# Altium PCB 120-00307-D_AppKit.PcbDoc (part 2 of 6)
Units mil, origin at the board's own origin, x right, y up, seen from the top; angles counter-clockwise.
Board outline 5150 x 3100 mil, 6 copper layers (L1, L2 (GND), L3-SIG, L4-SIG, L5 (PWR), L6), stack 61.956 mil thick; 413 components, 344 nets, 1685 pads, 1021 vias.
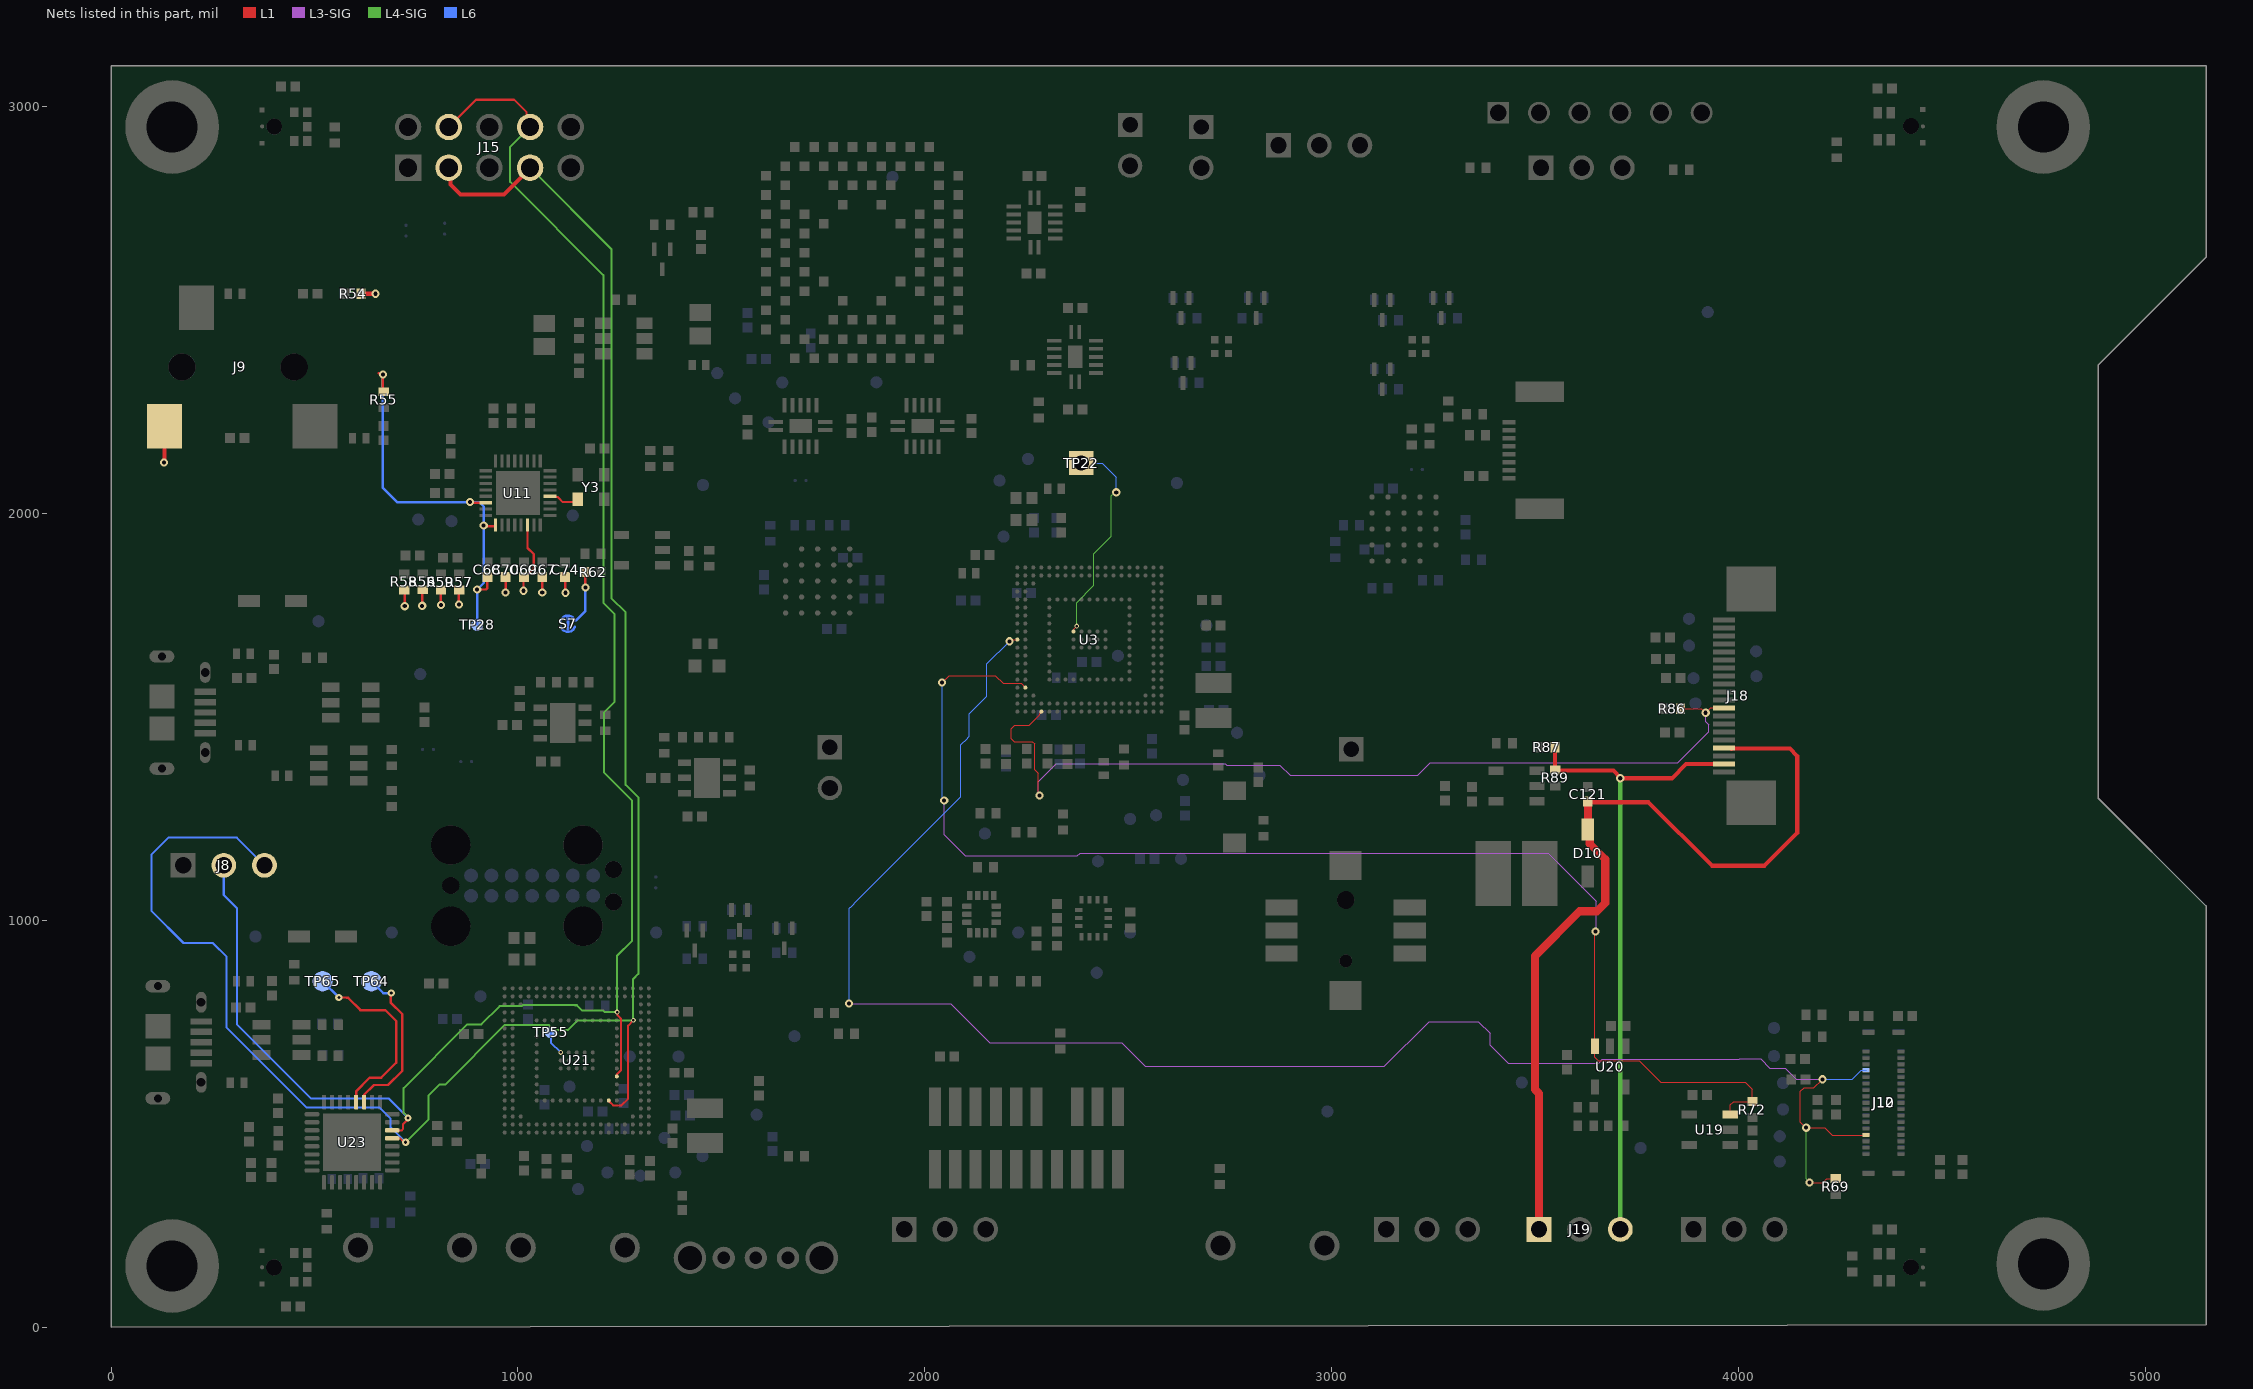
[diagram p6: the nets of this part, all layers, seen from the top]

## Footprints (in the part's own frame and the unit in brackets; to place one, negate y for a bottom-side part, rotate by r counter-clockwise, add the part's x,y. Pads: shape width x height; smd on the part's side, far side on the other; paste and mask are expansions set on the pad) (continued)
Solderbridge_Shorted#3 [mm]
  round 0.2 smd paste-10: 1(-0.338,0) 2(0.338,0)
  L1 region: 0.102,0.432 0.178,0.505 0.296,0.467 0.361,0.424 0.434,0.351 0.488,0.292 0.546,0.193 0.574,0.099 0.569,-0.122 0.544,-0.193 0.46,-0.33 0.376,-0.411 0.284,-0.469 0.183,-0.5 0.132,-0.483 0.102,-0.43
  L1 region: -0.102,-0.432 -0.178,-0.505 -0.296,-0.467 -0.361,-0.424 -0.434,-0.351 -0.488,-0.292 -0.546,-0.193 -0.574,-0.099 -0.569,0.122 -0.544,0.193 -0.46,0.33 -0.376,0.411 -0.284,0.469 -0.183,0.5 -0.132,0.483 -0.102,0.43
  L1 lines w0.152: -0.178,0.431 ccw(c-0.068,0) -0.178,-0.431 ; 0.178,0.431 cw(c0.068,0) 0.494,-0.127 cw(c0.068,0) 0.178,-0.431
  L1 lines w0.203: -0.338,0 0.338,0
Solderbridge_Shorted#4 [mm]
  round 0.2 smd paste-10: 1(-0.338,0) 2(0.338,0)
  L1 region: 0.102,0.432 0.178,0.505 0.296,0.467 0.361,0.424 0.434,0.351 0.488,0.292 0.546,0.193 0.574,0.099 0.569,-0.122 0.544,-0.193 0.46,-0.33 0.376,-0.411 0.284,-0.469 0.183,-0.5 0.132,-0.483 0.102,-0.43
  L1 region: -0.102,-0.432 -0.178,-0.505 -0.296,-0.467 -0.361,-0.424 -0.434,-0.351 -0.488,-0.292 -0.546,-0.193 -0.574,-0.099 -0.569,0.122 -0.544,0.193 -0.46,0.33 -0.376,0.411 -0.284,0.469 -0.183,0.5 -0.132,0.483 -0.102,0.43
  L1 lines w0.152: -0.178,0.431 ccw(c-0.068,0) -0.178,-0.431 ; 0.178,0.431 cw(c0.068,0) 0.178,-0.431
  L1 lines w0.203: -0.338,0 0.338,0
Solderbridge_Shorted#5 [mm]
  round 0.2 smd paste-10: 1(-0.338,0) 2(0.338,0)
  L1 region: 0.102,0.432 0.178,0.505 0.296,0.467 0.361,0.424 0.434,0.351 0.488,0.292 0.546,0.193 0.574,0.099 0.569,-0.122 0.544,-0.193 0.46,-0.33 0.376,-0.411 0.284,-0.469 0.183,-0.5 0.132,-0.483 0.102,-0.43
  L1 region: -0.102,-0.432 -0.178,-0.505 -0.296,-0.467 -0.361,-0.424 -0.434,-0.351 -0.488,-0.292 -0.546,-0.193 -0.574,-0.099 -0.569,0.122 -0.544,0.193 -0.46,0.33 -0.376,0.411 -0.284,0.469 -0.183,0.5 -0.132,0.483 -0.102,0.43
  L1 lines w0.152: -0.178,-0.431 cw(c-0.068,0) -0.254,0.404 cw(c-0.068,0) -0.178,0.431 ; 0.178,-0.431 ccw(c0.068,0) 0.279,0.391 ccw(c0.068,0) 0.254,0.404 ccw(c0.068,0) 0.203,0.423 ccw(c0.068,0) 0.178,0.431
  L1 lines w0.203: -0.338,0 0.338,0
Solderbridge_Shorted#6 [mm]
  round 0.2 smd paste-10: 1(-0.338,0) 2(0.338,0)
  L1 region: 0.102,0.432 0.178,0.505 0.296,0.467 0.361,0.424 0.434,0.351 0.488,0.292 0.546,0.193 0.574,0.099 0.569,-0.122 0.544,-0.193 0.46,-0.33 0.376,-0.411 0.284,-0.469 0.183,-0.5 0.132,-0.483 0.102,-0.43
  L1 region: -0.102,-0.432 -0.178,-0.505 -0.296,-0.467 -0.361,-0.424 -0.434,-0.351 -0.488,-0.292 -0.546,-0.193 -0.574,-0.099 -0.569,0.122 -0.544,0.193 -0.46,0.33 -0.376,0.411 -0.284,0.469 -0.183,0.5 -0.132,0.483 -0.102,0.43
  L1 lines w0.203: 0.338,0 -0.338,0
SSOT-6 [mm]
  rect 0.7x1 smd: 1(-0.95,-1.3) 2(0,-1.3) 3(0.95,-1.3) 4(0.95,1.3) 5(0,1.3) 6(-0.95,1.3)
  silkscreen extent -1.73,-1.17 1.5,0.8, body extent -1.48,-1.38 1.48,1.38, height 1.1
SW_1825966-TL1107-1 [mm]
  round 1.875 hole 1.25: 1(-3.25,0) 2(3.25,0)
  silkscreen extent -3,-1.75 3,1.75, body extent -3.9,-1.78 4,1.72, height 4.7
SW_JS1400BFQ [mm]
  rect 2x1 smd: 1(-4,1.425) 2(-4,0) 3(-4,-1.425) 4(4,1.425) 5(4,0) 6(4,-1.425)
  rect 2x1.8 smd: SH1(0,4.05) SH2(0,-4.05)
  round 0.8 hole 0.8 unplated: ""(0,1.9)
  round 1.1 hole 1.1 unplated: ""(0,-1.9)
  silkscreen extent -3.85,-3.7 3.85,3.7, body extent -4.5,-3.9 4.5,3.9, height 4.99
SW_SPDT_OS10201MSQN1 [mil] "Switch, SPDT slide, PCB vertical, 5 pin"
  round 55 hole 31: 1(-79,0) 2(0,0) 3(79,0)
  round 80 hole 59: 4(-162,0) 5(162,0)
  silkscreen extent -177,-109 176,90, body extent -168,-86 170,84, height 353
TC2070-IDC [mil]
  round 34 smd paste-42: 1(-150,-25) 2(-100,-25) 3(-50,-25) 4(0,-25) 5(50,-25) 6(100,-25) 7(150,-25) 8(150,25) 9(100,25) 10(50,25) 11(0,25) 12(-50,25) 13(-100,25) 14(-150,25)
  round 96.5 hole 96.5 unplated: 15(-200,100) 17(-200,-100) 18(125,-100) 21(125,100)
  round 42 hole 42 unplated: 16(-200,0) 19(200,-39.96) 20(200,39.96)
  silkscreen extent -249,-102 245,98
TP_30_RND [mil]
  round 30 smd paste-15: 1(0,0)
  silkscreen extent -22,-22 22,22
TP_50_RND [mil]
  round 50 smd paste-25: 1(0,0)
  silkscreen extent -32,-32 32,32
TSOT23-5_ONS [mil]
  rect 37.5x20 smd paste+0 mask+4: 1(-50.25,37.4) 2(-50.25,0) 3(-50.25,-37.4) 4(50.25,-37.4) 5(50.25,37.4)
  silkscreen extent -65,-62 37,75, body extent -55,-57 55,57, height 39
WE-TVS_SOT23-6L [mm] "TVS Diode, package SOT23-6L"
  rect 0.6x1.1 smd: 1(-0.95,-1.25) 2(0,-1.25) 3(0.95,-1.25) 4(0.95,1.25) 5(0,1.25) 6(-0.95,1.25)
  silkscreen extent -1.72,-1.37 1.45,0.45, body extent -1.45,-1.4 1.45,1.4, height 1.16
XTAL_ABS07_ABR-M [mil]
  rect 46x57 smd paste+0: 1(-64,0) 2(64,0)
  silkscreen extent -29,-33 29,33, body extent -65,-27 65,27, height 35

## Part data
C1 C7 C12 C13 C29 C30 C32 C33 C34 C35 C36 C73 C93 C95 C98 C99 C109 C112 C113 C114 C115 C128 C131 C141: "Cap,1.0uF,20%,25V,X5R,0402", Manufacturer 1=TDK, Manufacturer 2=Yageo, Manufacturer 3=Murata, Manufacturer Part Number 1=CGB2A1X5R1E105K033BC, Manufacturer Part Number 2=CC0402KRX5R8BB105, Manufacturer Part Number 3=GRM155R61E105KA12D, Tolerance=10%, Voltage=25V
C2 C5 C14 C49 C74 C88 C90 C92 C94 C96 C100 C117 C119: "Cap,10uF,20%,10V,X5R,0402", Manufacturer 1=AVX, Manufacturer 2=Samsung, Manufacturer 3=Venkel, Manufacturer Part Number 1=0402ZD106MAT2A, Manufacturer Part Number 2=CL05A106MP5NUNC, Manufacturer Part Number 3=C0402X5R100-106MNP, Tolerance=10%, Voltage=10V
C3 C8 C76: "Cap,10nF,10%,50V,X7R,0402", Manufacturer 1=TDK, Manufacturer 2=Samsung, Manufacturer 3=Walsin, Manufacturer Part Number 1=CGA2B3X7R1H103K050BE, Manufacturer Part Number 2=CL05B103KB5NNNC, Manufacturer Part Number 3=0402B103K500CT, Tolerance=10%, Voltage=50V
C4 C6 C11 C63 C71 C72 C78 C85 C86 C87 C89 C91 C97 C121 C122 C124: "Cap,2.2uF,20%,25V,X5R,0402", Manufacturer 1=TDK, Manufacturer 2=Murata, Manufacturer Part Number 1=C1005X5R1E225M050BC, Manufacturer Part Number 2=GRM155R61E225ME11D, Manufacturer Part Number 3=GRM155R61E225ME15D, Tolerance=20%, Voltage=25V
C9 C10 C15 C16 C17 C18 C19 C20 C21 C22 C23 C25 C26 C27 C28 C31 C37 C38 C39 C40 C41 C42 C45 C46 C47 C48 C57 C58 C59 C61 C62 C64 C65 C67 C75 C77 C79 C80 C81 C82 C83 C84 C101 C102 C103 C104 C105 C106 C107 C108 C110 C111 C116 C118 C120 C123 C125 C129 C133 C134: "Cap,100nF,10%,50V,X7R,0402", Manufacturer 1=TDK, Manufacturer 2=Samsung, Manufacturer 3=Walsin, Manufacturer Part Number 1=C1005X7R1H104K050BE, Manufacturer Part Number 2=CL05B104KB54PNC, Manufacturer Part Number 3=0402B104K500CT, Tolerance=10%, Voltage=50V
C24 C43 C44 C55 C56: "DNI, Cap,100nF,10%,50V,X7R,0402", Manufacturer 1=TDK, Manufacturer 2=Samsung, Manufacturer 3=Walsin, Manufacturer Part Number 1=C1005X7R1H104K050BE, Manufacturer Part Number 2=CL05B104KB54PNC, Manufacturer Part Number 3=0402B104K500CT, Tolerance=10%, Voltage=50V
C50 C51 C53 C60: "Cap,100pF,5%,25V,C0G,Hi-Q,0402", Manufacturer 1=Kemet, Manufacturer 3=Walsin, Manufacturer Part Number 1=CBR04C101J3GAC, Manufacturer Part Number 2=CBR04C101G3GAC, Manufacturer Part Number 3=RF15N101J250CT, Tolerance=5%, Voltage=25V
C52 C54: "Cap,100uF,20%,6.3V,X5R,0805", Manufacturer 1=MuRata, Manufacturer 2=Samsung, Manufacturer 3=Venkel, Manufacturer Part Number 1=GRM21BR60J107ME15K, Manufacturer Part Number 2=CL21A107MQYNNWE, Manufacturer Part Number 3=C0805X5R6R3-107MNE, Tolerance=20%, Voltage=6V3
C66 C68 C69 C70 C130 C132: library part Cap_225M25VX5R0402_1, "Cap,4.7uF,20%,10V,X5R,0402", Manufacturer 1=TDK, Manufacturer 2=Kyocera, Manufacturer 3=Samsung, Manufacturer Part Number 1=C1005X5R1A475K050BC, Manufacturer Part Number 2=0402YD475MAT2A, Manufacturer Part Number 3=CL05A475MP5NRNC, Tolerance=20%, Voltage=10V
C126 C127: library part Cap_SMT, "DNI,Cap,100pF,5%,50V,C0G,0402", Manufacturer 1=Kemet, Manufacturer 3=Walsin, Manufacturer Part Number 1=CBR04C101J3GAC, Manufacturer Part Number 2=CBR04C101G3GAC, Manufacturer Part Number 3=RF15N101J250CT, Tolerance=5%, Voltage=50V
D1 D3 D5: library part 82400102, "Diode,TVS  – High Speed Series, SOT23-6L, 2+1 Channel, 5Vdc, 2pF", Channel ESD Clamping Voltage=10V, Channel Input Capacitance=2pF, Channel Operating Voltage=5V, Channel Reverse Leakage Current=1uA, Manufacturer="Wurth Elektronik", Manufacturer 1=Wurth, Operating Temperature max.=125C, Operating Temperature min.=-40C, Reverse Breakdown Voltage=6V, Reverse Peak Pulse Current=7A
D2: "Diode,LED,Green 573nm,300mcd @ 20mA,0603", Manufacturer 1=Wurth, Manufacturer Part Number 1=150060VS86000
D4 D6 D9: library part "D LED_RGB_CA_1MMc1MM", "Diode,LED,RGB, (@2mA) -> R=10mcd & 1.75V, G = 50mcd & 2.75V, B = 20mcd & 2.95V, 0404(1mm x 1mm)", Manufacturer 1=Lumex
D7 D8 D10: "Diode,Schottky,2A,60V, <50uA@60V,SOD123F", Manufacturer 1=OnSemi, Manufacturer 2=Rohm, Manufacturer 3=Panjit, Manufacturer Part Number 1=SS26FL, Manufacturer Part Number 2=RB060MM-60TR, Manufacturer Part Number 3=SS2060FL_R1_00001
FB1 FB2 FB3 FB4 FB5 FB7 FB8 FB10 FB11 FB12: "Ind,WidebandChoke,1.5A,120ohm@100MHz,95mOhm,0402", Manufacturer 1=MuRata, Manufacturer Part Number 1=BLM15EG121SN1D, RMS_Current=1.5A
FB6 FB9: "DNI, Ind,WidebandChoke,1.5A,120ohm@100MHz,95mOhm,0402", Manufacturer 1=MuRata, Manufacturer Part Number 1=BLM15EG121SN1D, RMS_Current=1.5A
H1 H2 H3 H4: "Hole, #4,--not a BOM item--"
J1 J2: library part Conn_USB-5-6SHLD, "Conn,Micro USB B Type Receptacle,Right Angle", Manufacturer="Amphenol FCI", Manufacturer Part Number 1=10118194-0001LF, Package Description="5-Pin Surface Mount Device, Body 8.05 x 5.53 mm, Pitch 0.65 mm"
J3 J4 J21: library part Hdr_M_1X2_2M54_STRT_UNSHROUD, "Hdr, 0.025\" SQ Post Header, Through-hole, Vertical, -55 to 125 degC, 2.54 mm Pitch, 2-Pin, Male, RoHS", Manufacturer=Samtec, Manufacturer 2=Amphenol, Manufacturer Part Number 1=TSW-102-07-L-S, Manufacturer Part Number 2=77311-102-02LF, Temperature Range="-55 to 125 degC"
J5 J6 J11 J13 J16 J19: library part Hdr_M_1X3_2M54_STRT_UNSHROUD, "Hdr, 0.025\" SQ Post Header, Through-hole, Vertical, -55 to 125 degC, 2.54 mm Pitch, 3-Pin, Male, RoHS", Manufacturer=Samtec, Manufacturer 2=Sullins, Manufacturer 3=3M, Manufacturer Part Number 1=TSW-103-07-L-S, Manufacturer Part Number 2=PRPC003SAAN-RC, Manufacturer Part Number 3=929647-01-03-I, Temperature Range="-55 to 125 degC"
J7: library part Hdr_M_1X6_2M54_STRT_UNSHROUD, "Hdr, 0.025\" SQ Post Header, Through-hole, Vertical, -55 to 125 degC, 2.54 mm Pitch, 5-Pin, Male, RoHS", Manufacturer=Samtec, Temperature Range="-55 to 125 degC"
J8: library part Hdr_M_1X3_2M54_STRT_UNSHROUD, "DNI,Hdr, 0.025\" SQ Post Header, Through-hole, Vertical, -55 to 125 degC, 2.54 mm Pitch, 3-Pin, Male, RoHS", Manufacturer=Samtec, Manufacturer 2=Sullins, Manufacturer 3=3M, Manufacturer Part Number 2=PRPC003SAAN-RC, Manufacturer Part Number 3=929647-01-03-I, Temperature Range="-55 to 125 degC"
J9: library part CONN_AUDIO_SJ-3523-SMT-TR, "Conn, Audio Jack, 3.5 mm Low Profile Surface Mount Stereo Jack, 3 Pin Right-Angle", Manufacturer 1=CUI, Manufacturer Part Number 1=SJ-3523-SMT-TR, Package=None
J10 J12: library part CONN_HIROSE_BM20_FPC_34PIN_0.4MM, "Conn,FPC,34 pin,0.4mm pitch, 0,8mm height,SMT", Manufacturer 1=HiRose
J14: "Test Point, Array, Alignment Pins, SMT Pad,--not a BOM item--"
J15: library part Hdr_M_2X5_2M54_STRT_UNSHROUDED, "Hdr, Male,2x5, 2.54mm, 0.230mate,0.100-0.120post,Strt", Manufacturer 1=Samtec, Manufacturer 2=Sullins, Manufacturer Part Number 1=TSW-105-07-L-D, Manufacturer Part Number 2=PBC05DAAN, Manufacturer Part Number 3=TSW-105-07-F-D
J17: "Hdr,Male,2x10,1.27mm,Strt,Keyed,Cortex-JTAG", Manufacturer 1=Samtec, Manufacturer Part Number 1=FTSH-110-01-L-DV-007-K
J18: library part Conn_FFC_TOP_SLIDEorLOCK_0.50_20pin, "Conn,FlatFlex,20 pin,0.50mm,top-entry,slide-flap,SMT", Manufacturer 1=Amphenol, Manufacturer 2=Molex, Manufacturer Part Number 2=0527452097
J20: library part Conn_FFC_TOP_SLIDorLOCK_0.50_8pin, "Conn,FlatFlex,8 pin,0.50mm,top-entry,slide-flap,SMT", Manufacturer 1=Amphenol, Manufacturer 2=Molex, Manufacturer 3=TE, Manufacturer Part Number 2=0527450897, Manufacturer Part Number 3=1734839-8, Mfr_Name=Omron
L3 L4: "Ind,Unshielded,2.2uH,20%,2.3A,85mOhm,1008(2520)", Manufacturer 1=MuRata, Manufacturer 2="Pulse Eng", Manufacturer 3=Vishay, Manufacturer Part Number 1=DFE252012F-2R2M{}P2, Manufacturer Part Number 2=BDHE002520122R2MQ1, Manufacturer Part Number 3=IHHP1008ABER2R2M01, RMS_Current=2.3A, Tolerance=20%
L5: "Ind,Shielded,22uH,20%,700mA,350mOhm,4x4x2mm", Manufacturer 1=Vishay, Manufacturer 2=Yageo, Manufacturer 3=Abracon, Manufacturer Part Number 1=IFSC1515AHER220M0, Manufacturer Part Number 2=BWVS00404018220M00, Manufacturer Part Number 3=ASPI-0418FS-220M-T3, RMS_Current=700mA, Tolerance=20%
Q1 Q2 Q3 Q4 Q5 Q6 Q8 Q9 Q10 Q11: "MOSFET,N-CH,20V,250mA,1.1Ohm,SOT-23", Manufacturer 1=Toshiba, Manufacturer 2=Rohm, Manufacturer Part Number 1=SSM3K35AFS, Manufacturer Part Number 2=RUE002N02TL
Q7: library part FET_PMOS_6P, "MOSFET,P-CH,20V,4.5A,48mOhm,SSOT-6", Continuous Drain Current=-4.5A, Drain To Source Breakdown Voltage=-20V, Drain To Source Resistance=0.041Ω, Drain To Source Voltage=-30V, Gate To Source Voltage=20V, Input Capacitace At Vds="750pF @ -15V", Manufacturer="ON Semiconductor", Manufacturer 1=OnSemi, Manufacturer 2=Fairchild, Manufacturer Part Number 1=FDC658P, Max Forward Diode Voltage=-1.2V, Max Junction Temp=+150°C, Power Dissipation=0.8W, Pulse Drain Current=-20A, Temperature="-55°C to +150°C", Temperature Range Low=-55°C, Typ Forward Diode Voltage=-0.76V
R1 R56 R57: "Res,33K2,1%,100ppm,0402", Manufacturer 1=Stackpol, Manufacturer 2=Yageo, Manufacturer 3=Bourns, Manufacturer Part Number 1=RMCF0402FT33K2, Manufacturer Part Number 2=RC0402FR-0733K2L, Manufacturer Part Number 3=CR0402-FX-3322GLF, Tolerance=1%
R2 R16 R32 R33 R34 R35 R97 R98 R105 R106 R107 R108 R109 R110: "Res,0R ohm,Jumper,0402", Manufacturer 1=Stackpol, Manufacturer 2=Yageo, Manufacturer 3=Panasonic, Manufacturer Part Number 1=RMCF0402ZT0R00, Manufacturer Part Number 2=RC0402FR-070RL, Manufacturer Part Number 3=ERJ-XGN0R00Y, Tolerance=JMPR
R3 R9 R12 R26 R31 R61 R69 R71 R86 R90 R93 R101 R104: "Res,10K0,1%,100ppm,0402", Manufacturer 1=Stackpol, Manufacturer 2=Yageo, Manufacturer 3=Bourns, Manufacturer Part Number 1=RMCF0402FT10K0, Manufacturer Part Number 2=RC0402FR-0710KL, Manufacturer Part Number 3=CR0402-FX-1002GLF, Tolerance=1%
R4 R8 R10 R62 R74 R100 R103: "Res,20K0,1%,100ppm,0402", Manufacturer 1=Stackpol, Manufacturer 2=Yageo, Manufacturer 3=Bourns, Manufacturer Part Number 1=RMCF0402FT20K0, Manufacturer Part Number 2=RC0402FR-0720KL, Manufacturer Part Number 3=CR0402-FX-2002GLF, Tolerance=1%
R5 R48 R49 R50 R51 R52 R53: "Res,1K82,1%,100ppm,0402", Manufacturer 1=Stackpol, Manufacturer 2=Yageo, Manufacturer 3=Bourns, Manufacturer Part Number 1=RMCF0402FT1K82, Manufacturer Part Number 2=RC0402FR-071K82L, Manufacturer Part Number 3=CR0402-FX-1821GLF, Tolerance=1%
R6 R11 R29 R30: "DNI,Res,100K,1%,100ppm,0402", Manufacturer 1=Stackpol, Manufacturer 2=Yageo, Manufacturer 3=Bourns, Manufacturer Part Number 1=RMCF0402FT100K, Manufacturer Part Number 2=RC0402FR-07100KL, Manufacturer Part Number 3=CR0402-FX-1003GLF, Tolerance=1%
R7: "Res,8K66,1%,100ppm,0402", Manufacturer 1=Stackpol, Manufacturer 2=Yageo, Manufacturer 3=Bourns, Manufacturer Part Number 1=RMCF0402FT8K66, Manufacturer Part Number 2=RC0402FR-078K66L, Manufacturer Part Number 3=CR0402-FX-8661GLF, Tolerance=1%
R13 R20 R79: "Res,681R,1%,100ppm,0402", Manufacturer 1=Stackpol, Manufacturer 2=Yageo, Manufacturer 3=Bourns, Manufacturer Part Number 1=RMCF0402FT681R, Manufacturer Part Number 2=RC0402FR-07681RL, Manufacturer Part Number 3=CR0402-FX-6810GLF, Tolerance=1%
R14 R17 R21 R23 R41 R80 R82 R87: "Res,1K00,1%,100ppm,0402", Manufacturer 1=Stackpol, Manufacturer 2=Yageo, Manufacturer 3=Bourns, Manufacturer Part Number 1=RMCF0402FT1K, Manufacturer Part Number 2=RC0402FR-071KL, Manufacturer Part Number 3=CR0402-FX-1001GLF, Tolerance=1%
R15 R18 R19 R22 R24 R25 R27 R28 R39 R40 R43 R44 R45 R60 R63 R66 R72 R78 R81 R83 R84 R85 R88 R94: "Res,100K,1%,100ppm,0402", Manufacturer 1=Stackpol, Manufacturer 2=Yageo, Manufacturer 3=Bourns, Manufacturer Part Number 1=RMCF0402FT100K, Manufacturer Part Number 2=RC0402FR-07100KL, Manufacturer Part Number 3=CR0402-FX-1003GLF, Tolerance=1%
R36 R37 R76: "Res,200R,1%,100ppm,0402", Manufacturer 1=Stackpol, Manufacturer 2=Yageo, Manufacturer 3=Bourns, Manufacturer Part Number 1=RMCF0402FT220R, Manufacturer Part Number 2=RC0402FR-07200RL, Manufacturer Part Number 3=CR0402-FX-2000GLF, Tolerance=1%
R42 R75 R95 R96 R111: "DNI,Res,0R ohm,Jumper,0402", Manufacturer 1=Stackpol, Manufacturer 2=Yageo, Manufacturer 3=Panasonic, Manufacturer Part Number 1=RMCF0402ZT0R00, Manufacturer Part Number 2=RC0402FR-070RL, Manufacturer Part Number 3=ERJ-XGN0R00Y, Tolerance=JMPR
R46 R47 R92: "DNI,Res,4K75,1%,100ppm,0402", Manufacturer 1=Stackpol, Manufacturer 2=Yageo, Manufacturer 3=Bourns, Manufacturer Part Number 1=RMCF0402FT4K75, Manufacturer Part Number 2=RC0402FR-074K75L, Manufacturer Part Number 3=CR0402-FX-4751GLF, Tolerance=1%
R54 R55 R58 R59: "Res,20R0,1%,100ppm,0402", Manufacturer 1=Stackpol, Manufacturer 2=Yageo, Manufacturer 3=Bourns, Manufacturer Part Number 1=RMCF0402FT20R, Manufacturer Part Number 2=RC0402FR-0720RL, Manufacturer Part Number 3=CR0402-FX-20R0GLF, Tolerance=1%
R64 R65 R67 R68: "Res,33R2,1%,100ppm,0402", Manufacturer 1=Stackpol, Manufacturer 2=Yageo, Manufacturer 3=Bourns, Manufacturer Part Number 1=RMCF0402FT33R2, Manufacturer Part Number 2=RC0402FR-0733R2L, Manufacturer Part Number 3=CR0402-FX-33R2GLF, Tolerance=1%
R70: "Res,23K7,1%,100ppm,0402", Manufacturer 1=Stackpol, Manufacturer 2=Yageo, Manufacturer 3=Bourns, Manufacturer Part Number 1=RMCF0402FT23K7, Manufacturer Part Number 2=RC0402FR-0723K7L, Manufacturer Part Number 3=CR0402-FX-2372GLF, Tolerance=1%
R73: "Res,150K,1%,100ppm,0402", Manufacturer 1=Stackpol, Manufacturer 2=Yageo, Manufacturer 3=Bourns, Manufacturer Part Number 1=RMCF0402FT150K, Manufacturer Part Number 2=RC0402FR-07150KL, Manufacturer Part Number 3=CR0402-FX-1503GLF, Tolerance=1%
R89: "Res,7R50,1%,100ppm,0402", Manufacturer 1=Stackpol, Manufacturer 2=Yageo, Manufacturer Part Number 1=RMCF0402FT7R5, Manufacturer Part Number 2=RC0402FR-077R5L, Tolerance=1%
R91 R99 R102: "Res,4K75,1%,100ppm,0402", Manufacturer 1=Stackpol, Manufacturer 2=Yageo, Manufacturer 3=Bourns, Manufacturer Part Number 1=RMCF0402FT4K75, Manufacturer Part Number 2=RC0402FR-074K75L, Manufacturer Part Number 3=CR0402-FX-4751GLF, Tolerance=1%
S1 S2 S3 S5 S6 S7 S8 S9: "DNI,Solderable Jumper,Shorted"
SW1 SW4 SW5: "Swit, SPST, Momentary Pushputton, 2 pin, 6.0x3.5mm, H=5.0mm", Manufacturer 1=E-Switch, Manufacturer 2=C&K, Manufacturer 3=Panasonic, Manufacturer Part Number 1=TL1107BF180WQ, Manufacturer Part Number 2="PTS636 SM50 LFS", Manufacturer Part Number 3=EVQ-PE505K
SW2: "Navigation Switch, 2 - Axis Digital (Mechanical Switch) Output", Manufacturer 1=ESwitch, Manufacturer 2=Diptronics, Manufacturer Part Number 1=JS1400BFQ, Manufacturer Part Number 2=MT5-1F-V, Package=None
SW3: library part SW-SPDT_Vert-5P, "Switch,SPDT, 12V, 50mA, Non-Shorting, 5 Pin PCB Vertical", Manufacturer 1=C&K, Manufacturer 3=E-Switch, Manufacturer Part Number 1=OS102011MS2QN1, Manufacturer Part Number 2=OS102011MS2QN1C, Manufacturer Part Number 3=EG1249
TP1 TP2 TP3 TP4 TP5 TP6 TP7 TP8 TP9 TP10 TP11 TP12 TP13 TP14 TP15 TP16 TP17 TP18 TP19 TP20 TP21 TP25 TP26 TP27 TP28 TP29 TP30 TP31 TP32 TP33 TP34 TP35 TP36 TP37 TP38 TP39 TP40 TP41 TP42 TP43 TP44 TP45 TP46 TP47 TP48 TP49 TP50 TP51 TP52 TP53 TP54 TP55 TP56 TP58 TP59 TP60 TP61 TP62 TP63 TP66 TP67 TP68 TP69 TP70: "Test Point, SMT Pad,--not a BOM item--"
TP22 TP23: library part Hdr_M_1X1_2M54_STRT_UNSHROUD, "DNI,Hdr, 0.025\" SQ Post Header, Through-hole, Vertical, -55 to 125 degC, 2.54 mm Pitch, 1-Pin, Male, RoHS", Manufacturer=Samtec, Manufacturer 2=Amphenol, Manufacturer Part Number 1=TSW-101-07-L-S, Manufacturer Part Number 2=77311-101-01LF, Temperature Range="-55 to 125 degC"
TP64 TP65: "DNI,Test Point, SMT Pad,--not a BOM item--"
U1 U2: library part IC_LDO_NCP690MNADJT2G, "IC, LDO,Adj 1.25V - 5.5V,1.0A,+ Enable,DFN6", Manufacturer 1=OnSemi
U3: library part E7_B0_194BGA, "IC,Alif E7 MCU, Rev B silicon, 5.5MB MRAM, 13.5MB SRAM, BGA194", Manufacturer 1="Alif Semi", Manufacturer Part Number 1=AE722F80F55D5LS
U4: "IC, Flash,64MB x 8, Octal SPI, Ind Temp, 1.8V,24-BGA", Manufacturer 1=ISSI, Manufacturer Part Number 1=IS25WX512M-JHLE, Package="BGA-24 Dialog Semiconductor"
U5: "IC, Hyper PSRAM,64MB x 8, Octal SPI, Ind Temp, 1.8V,24-BGA", Manufacturer 1=ISSI, Manufacturer Part Number 1=IS66WVH64M8DALL-166B1LI
U6: library part IC_XLAT_NTB0104BQ, "DNI,IC, Voltage Level Translator, 4-bit,push-pull,50Mbps,VCC(A): 1.2 V to 3.6 V and VCC(B): 1.65 V to 5.5 V,auto-sense,DHVQFN14(2.5x3.0)", Arrow Part Number=NTB0104BQ-Q100X, Manufacturer 1=NXP, Manufacturer Part Number 3=NTB0104BQ,115, Mouser Part Number=771-NTB0104BQQ100X
U7: library part MOD_WE310F5-I, "Module, WIFI (802.11 b/g/n) / BLE (5.0) MODULE, SMD-94P", Manufacturer 1=Telit, Manufacturer Part Number 1=WE310F5I396R001000, Manufacturer Part Number 2=WE310F5I396T001000, Operating_Temp="-40C TO +85C"
U8 U9: library part IC_XLAT_NTB0104BQ, "IC, Voltage Level Translator, 4-bit,push-pull,50Mbps,VCC(A): 1.2 V to 3.6 V and VCC(B): 1.65 V to 5.5 V,auto-sense,DHVQFN14(2.5x3.0)", Arrow Part Number=NTB0104BQ-Q100X, Manufacturer 1=NXP, Manufacturer Part Number 3=NTB0104BQ,115, Mouser Part Number=771-NTB0104BQQ100X
U10: library part IC_XLAT_NTS0104BQ, "DNI,IC, Voltage Level Translator, 4-bit,open-drain,50Mbps,VCC(A): 1.2 V to 3.6 V and VCC(B): 1.65 V to 5.5 V,auto-sense,DHVQFN14(2.5x3.0)", Arrow Part Number=NTB0104BQ-Q100X, Manufacturer 1=NXP, Manufacturer Part Number 2=NTS0104BQ-Q100X, Manufacturer Part Number 3=NTS0104BQ,115, Mouser Part Number=771-NTB0104BQQ100X
U11: library part IC_CODEC_WM8904CGEFL_V, "IC, Audio CODEC, Ultra Low Pwr, 1.8V, QFN33", Manufacturer 1="Cirrus Logic", Manufacturer Part Number 1=WM8904CGEFL/V, Mouser Part Number=238-WM8904CGEFL/V
U12 U19 U20: library part IC_LDO_NCV8164ASNADJT1G, "IC, LDO,Adj 1.2V - 5.5V,300mA,SOT23-5", Manufacturer 1=OnSemi
U13 U15: library part MIC_T5848, "IC,Microphone,I2S,Bottom Port,Sens -37db,SNR 68dbA,AOP 13db SPL,1.8V", Manufacturer 1=TDK/Invensense, Manufacturer Part Number 1=T5848-00-012, Manufacturer_Name=TDK
U14: "IC, IMU Gyro & Accel, I3C, 1.8V, LGA14", Manufacturer 1=TDK_Invensense, Manufacturer Part Number 1=ICM-42670-P
U16: library part IC_IMU_BMI323, "IC,IMU,6 Axis Sensor I3C, SPI, LGA14", Manufacturer 1=Bosch, Package="LGA-14 Bosch"
U17 U18: library part MIC_T5838, "IC,Microphone,PDM,Bottom Port,Sens -37db,SNR 68dbA,AOP 13db SPL,1.8V", Manufacturer 1=TDK, Manufacturer Part Number 1=MMICT5838-00-012
U21: library part E7_B0_194BGA, "IC,Alif E1 MCU, Rev B silicon,1.5MB MRAM, 4.5MB SRAM. BGA194", Manufacturer 1="Alif Semi", Manufacturer Part Number 1=AE101F4071542LH
U22: library part IC_BOOST_CAT4139TD-GT3, "IC, Boost Converter, LED Driver", Manufacturer 1=OnSemi
U23: library part IC_Dual_USB_UART_Bridge, "IC,Dual USB to Serial Bridge,32QFN", Ambient Temperature Range High=+85°C, Ambient Temperature Range Low=-40°C, Manufacturer 1=Cypress, Max Supply Voltage=5.5V, Min Supply Voltage=1.71V, Nominal Supply Current=13mA, Package=001-30999, Temperature="-40°C to +85°C"
Y1 Y4: "Crystal,38.4MHz,20ppm,6.0pF,100ohm,2016-4pin", Manufacturer 1=Murata, Manufacturer Part Number 1=XRCGB38M400F2P00R0
Y2: "Crystal,32.768KHz,20ppm,6.0pF,100ohm,3215-4pin", Manufacturer 1=Abracon, Manufacturer Part Number 1=ABS07-32.768KHZ-6-T
Y3: library part Osc_12M288_20ppm_1V8_3225, "Oscillator,XO,12.288MHz,20ppm,1.8V,3225(1210)-4P", Manufacturer 1=Microchip, Manufacturer 2=Kyocera, Manufacturer 3=SiTime, Manufacturer Part Number 1=DSC1001DL5-012.2880, Manufacturer Part Number 2=KC2520Z12.2880C1KX00, Manufacturer Part Number 3=SIT8008BI-11-18E-12.288000, Tolerance=20ppm

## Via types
v1: diameter 20, hole 10, L1 to L6, tented both sides, 437 vias
v2: diameter 20, hole 10, L1 to L6, 330 vias
v3: diameter 12, hole 6, L1 to L6, tented both sides, 120 vias
v4: diameter 18, hole 8, L1 to L6, 93 vias
v5: diameter 16, hole 8, L1 to L6, tented both sides, 41 vias

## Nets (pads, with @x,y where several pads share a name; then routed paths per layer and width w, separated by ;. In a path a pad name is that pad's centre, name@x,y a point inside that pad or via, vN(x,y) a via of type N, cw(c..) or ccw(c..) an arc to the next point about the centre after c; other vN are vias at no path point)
AG: C67.1 C68.1 C69.1 C70.1 C74.1 J9.1 R54.1 R55.1 R56.2 R57.2 R58.2 R59.2 R62.2 S7.2 TP28.1 U11.14 U11.17 U11.22 | length 1722
  L1 w6: 657.49,2345 657.81,2344.68 667,2344.68 v2@667,2341 ; R55.1@668,2298 v2(668,2342) ; R58.2@719,1810 722,1813 R58.2@721,1813 ; v1(721.84,1771.97) R58.2@721.84,1809.29 ; v1(764.84,1772.97) R56.2@764.84,1810.29 ; v1(810.84,1774.97) R59.2@810.84,1812.29 ; v1(854.84,1775.97) R57.2@854.84,1813.29 ; v1(882,2028) 883.62,2026.38 U11.14@921.26,2026.38 ; v1(900,1813) 921.49,1813 925,1816.51 C68.1@925,1843.6 ; v1@917,1969 943.94,1969 944.88,1969.94 U11.17@944.88,1971.26 ; v1(969.84,1805.97) C70.1@969.84,1843.29 ; v1(1013.84,1809.97) C69.1@1013.84,1847.29 ; C69.1@1015,1843.6 1015.4,1843.6 C69.1@1018,1841 ; U11.22@1023.62,1971.26 1023.62,1915.38 1039,1900 1039,1864 C69.1@1024,1849 ; v1(1059.84,1805.97) C67.1@1059.84,1843.29 ; v1(1116.84,1804.97) C74.1@1116.84,1842.29 ; R62.2@1165.31,1856 1166,1855.31 v1(1166,1818)
  L1 w10: v2(130,2125) 131.1,2126.1 J9.1@131.1,2214.33 ; R54.1@614.68,2540 v2(650,2540)
  L6 w6: v2(668,2342) 668,2063 703,2028 v1(882,2028) 905,2028 916,2017 v1(916,1970) 916,1829 v1(900,1813) TP28.1@900,1728 ; 1139.67,1737 1143,1737 1166,1760 v1(1166,1818)
AMUX_P: TP22.1 U3.J8 | length 525.2
  L1 w3: U3.J8@2365.63,1709.68 2366.82,1710.87 2366.82,1715.82 v3(2374,1723)
  L4-SIG w3: v3(2374,1723) 2374,1781 2416,1823 2416,1901 2459,1944 2459,2043 2468,2052 v2(2471,2052)
  L6 w3: TP22.1@2385,2124 2436,2124 2471,2089 v2(2471,2052)
AMUX_P_J: TP55.1 U21.J8 | length 60.1
  L6 w5: TP55.1@1081,725 1081,699.32 v3(1105.32,675)
BL_LED_A: C121.2 D10.1 J18.4 J19.1 | length 2160.7
  L1 w10: C121.2@3630,1292.28 3630,1291 3631,1290 3779,1290 3935,1134 4065,1134 4145,1214 4145,1404 4127,1422 3984,1422 J18.4@3983,1421 ; J18.4@3965,1423.46 J18.4@3983,1423.46
  L1 w20: J19.1@3510,240 3510,574 3500,584 3500,912 3610,1022 3653,1022 3673,1042 3673,1150 3635,1188 3635,1219 3631,1223 C121.2@3631,1290
BL_LED_K: J18.2 J19.3 R87.1 R89.2 | length 1592.2
  L1 w10: R87.1@3549.37,1425 3550,1424.37 R89.2@3550,1369.37 R89.2@3550,1364 ; R89.2@3552,1368 3693,1368 v2@3711,1350 ; v2(3710,1349) 3837,1349 3872,1384 J18.2@3951,1384
  L4-SIG w10: J19.3@3710,240 v2(3710,1349)
C_EN_MIPI_PWR: R72.2 U3.T2 U19.3 U20.3 | length 3193.2
  L1 w3: v2(2043,1584) 2060,1601 2174,1601 2193,1582 2237.41,1582 U3.T2@2247.52,1571.89 ; v2(3649,972) 3647.6,970.6 3647.6,663.4 3656,655 3757,655 3810,602 4017,602 4035,584 R72.2@4035,554.37 3988.37,554.37 3980.25,546.25 U19.3@3980.25,522.4
  L3-SIG w3: v2(2048,1294) 2048,1210 2100,1158 2375.49,1158 2382.66,1165.17 3532.83,1165.17 3651.26,1046.74 3651.26,974.26 v2(3649,972)
  L6 w3: v2(2043,1584) 2043,1299 v2(2048,1294)
C_RESETn: J10.21 J12.21 R69.2 U3.K1 | length 4301.2
  L1 w3: v2(2208.64,1685.68) 2209.91,1684.4 2212.4,1684.4 2218,1690 U3.K1@2227.84,1690 ; v2(4175,355) 4208,355 4218,365 R69.2@4240,365 ; v2@4206,608 4186,588 4162,588 4153,579 4153,504 v2(4167,490) 4213,490 4230.99,472.01 J10.21@4314.17,472.01
  L3-SIG w3: v2(1814,795) 2064,795 2160.5,698.5 2484.5,698.5 2542,641 3130,641 3240,751 3361,751 3390,722 3390,693 3435,648 3509,648 3510,649 3657,649 3666,658 4003,658 4004,659 4055,659 4078,636 4116,636 4143,609 v2(4207,609)
  L4-SIG w3: v2@4167,489 4167,365.02 4175,357.02 v2(4175,355)
  L6 w3: v2(1814,795) 1814,1029 1817.5,1032.5 1818.01,1032.5 1826.5,1040.99 1826.5,1041.5 2089,1304 2089,1431 2105.5,1447.5 2105.5,1447.99 2109.5,1451.99 2109.5,1507.5 2153,1551 2153,1630.04 v2(2208.64,1685.68) ; v2(4207,609) 4280,609 4302.73,631.73 J12.21@4314.17,631.73
C_RXD: J8.3 J15.3 J15.7 U21.R14 U23.5 | length 4952.8
  L1 w5: U23.5@685,464 710.67,464 718.67,456 v4@725,456 ; U21.R14@1223.43,556.89 1223.43,555.58 1225.85,553.16 1234,545 1254.72,545 1271,561.28 1271,741 v3(1284,754)
  L1 w10: J15.3@830,2850 834.64,2845.36 834.64,2808.36 859,2784 966,2784 J15.7@1029,2847
  L4-SIG w5: v4(724,454) 780,510 780,569 807,596 821,596 967,742 1076,742 1088,730 1123,730 1147,754 v3(1284,754) 1283,755 1283,855 1296,868 1296,1302 1265,1333 1265,1757 1230,1792 1230,2650 J15.7@1030,2850
  L6 w5: J8.3@377,1135 309,1203 141,1203 99,1161 99,1023 178,944 250,944 284,910 284,736 480,540 659,540 687,512 687,491 v4(724,454)
C_TXD: J8.2 J15.4 J15.8 U21.M15 U23.6 | length 4474.3
  L1 w5: U23.6@685,483.69 714.69,483.69 718,487 718,499.13 730,511.13 v4(730,514) ; J15.4@830,2950 897,3017 991,3017 1020.93,2987.07 1020.93,2959.07 J15.8@1030,2950 ; U21.M15@1243.11,615.94 1244.04,616.87 1244.04,621.98 1247.27,625.21 1247.43,625.21 1253.53,631.31 1253.53,758.06 1245.34,766.25 1245.34,772.66 v3(1244,774)
  L4-SIG w5: v4(730,514) 730,515.33 719,526.33 719,587 876,744 910,744 955,789 1010,789 1012.49,791.49 1139.75,791.49 1140.24,791 1145,791 1158,778 1210,778 1214,774 v3(1244,774) 1243.11,774.89 1243.11,912.11 1281,950 1281,1294 1212,1363 1212,1511 1238,1537 1238,1752 1210,1780 1210,2586 981,2815 981,2901 J15.8@1030,2950
  L6 w5: J8.2@278,1131 277,1130 277,1062 309,1030 309,744 491,562 682,562 v4(730,514)
CLK_CODEC: U11.28 Y3.3 | length 74.1
  L1 w5: U11.28@1078.74,2042.13 1080.18,2040.69 1097.31,2040.69 1099.98,2038.02 1110,2028 Y3.3@1147,2028
D_RESETn: J18.9 R86.2 U3.W4 | length 2235.7
  L1 w3: v2(2282,1307) 2279,1310 2279,1361 2270,1370 2270,1434 2265,1439 2220,1439 2213,1446 2213,1471 2221.5,1479.5 2256.99,1479.5 2283,1505.51 2283,1507.09 2286.89,1510.98 U3.W4@2286.89,1512.84 ; R86.2@3857.69,1520 3857.94,1519.75 3909.24,1519.75 3918.98,1510 v2(3920,1510) 3931.89,1521.89 J18.9@3965,1521.89
  L3-SIG w3: v2(2282,1307) 2279,1310 2279,1340 2324,1385 2739.11,1385 2742.61,1381.5 2873.5,1381.5 2899,1356 3212,1356 3243,1387 3851,1387 3927,1463 3927,1480.7 3920,1487.7 v2(3920,1510)
FTDI_SUSPEND: TP64.1 U23.11 | length 421.5
  L1 w6: U23.11@621.96,546.73 621.96,570.96 646,595 681,595 716,630 716,769 688,797 688,821 v4(689,821)
  L6 w6: TP64.1@630,860 TP64.1@640,850 669,821 v4(689,821)
FTDI_WAKEUP: TP65.1 U23.12 | length 484.2
  L1 w6: v4(560,810) 579,810 580,809 583,809 613,779 674,779 701,752 701,650 664,613 636,613 602.27,579.27 U23.12@602.27,546.73
  L6 w6: TP65.1@520,850 v4(560,810)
